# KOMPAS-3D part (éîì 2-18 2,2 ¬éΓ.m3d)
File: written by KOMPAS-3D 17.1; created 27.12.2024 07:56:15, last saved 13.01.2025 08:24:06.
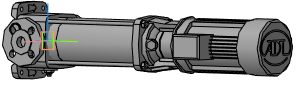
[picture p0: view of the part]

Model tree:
1. Операция без истории:4  (labels: ВМН 2-18 2,2 кВт)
